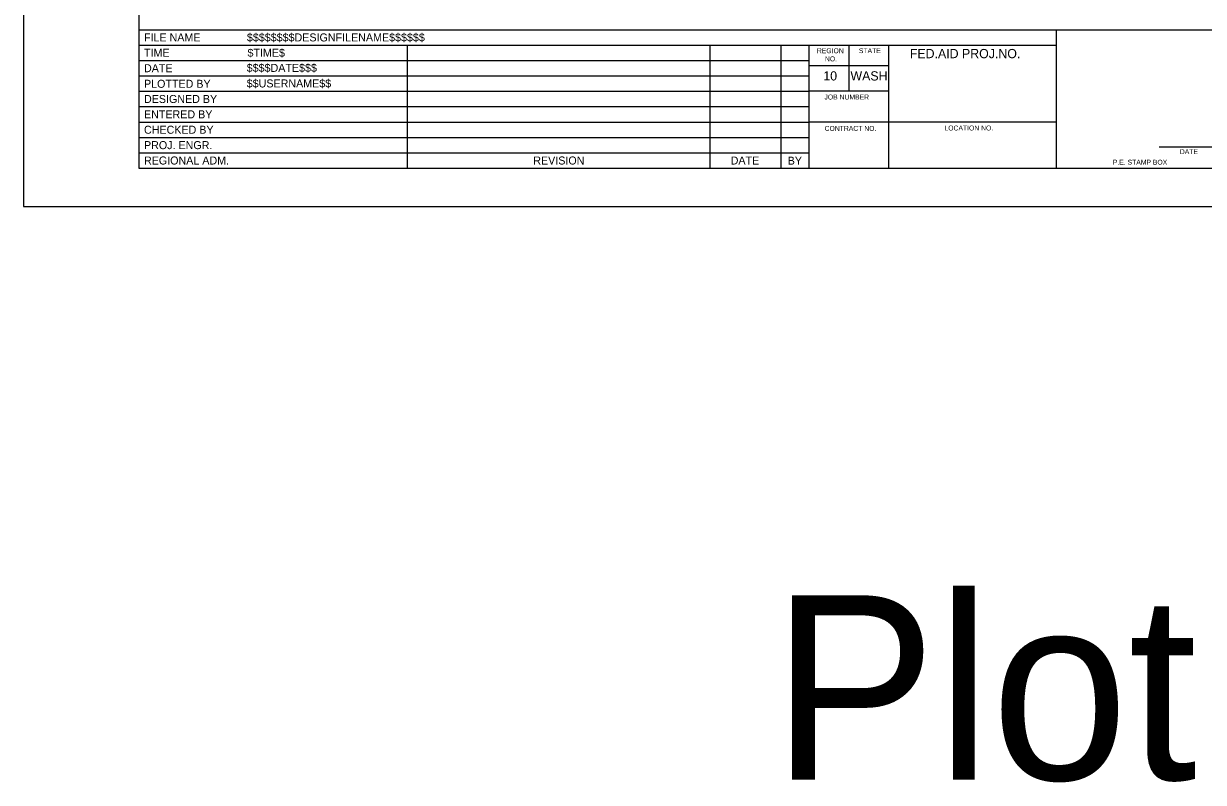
# Model space of a CAD drawing. Extents: x 99999.1 to 100035.7, y 99995 to 100010.7.
# Drawn here: x 99999.06 to 100008.65, y 99995.01 to 100001.18 of the extents above; entities that cross this region are included whole.
import ezdxf

# ---------------------------------------------------------------- set-up
doc = ezdxf.new("R2010")
doc.units = 0
for name, color, linetype in [('SH_GI_PlotLimits', 7, 'Continuous'), ('SH_GI_SheetBorder', 7, 'Continuous'), ('SH_GI_SheetLocationText', 7, 'Continuous'), ('SH_GI_SheetTextInCells', 7, 'Continuous'), ('SH_GI_TitleBlockText', 7, 'Continuous')]:
    doc.layers.add(name, color=color, linetype=linetype)

msp = doc.modelspace()

# ---------------------------------------------------------------- linework, layer by layer
at = {"layer": 'SH_GI_PlotLimits'}
msp.add_lwpolyline([(99999.0625, 99999.6875), (100016.0625, 99999.6875), (100016.0625, 100010.6875), (99999.0625, 100010.6875)], close=True, dxfattribs=at)
at = {"layer": 'SH_GI_SheetBorder'}
for p, q in [((100000, 100010.375), (100000, 100000)), ((100000, 100001.1259), (100015.75, 100001.1259)), ((100007.4566, 100000), (100007.4566, 100001.1259)), ((100000, 100001.0008), (100007.4566, 100001.0008)), ((100002.179, 100001.0008), (100002.179, 100000)), ((100004.641, 100001.0008), (100004.641, 100000)), ((100005.2164, 100001.0008), (100005.2164, 100000)), ((100005.4451, 100001.0008), (100005.4451, 100000)), ((100005.7719, 100000.6255), (100005.7719, 100001.0008)), ((100006.0956, 100000), (100006.0956, 100001.0008)), ((100000, 100000.8757), (100002.1821, 100000.8757)), ((100002.1821, 100000.8757), (100005.4466, 100000.8757)), ((100000, 100000.7506), (100002.1821, 100000.7506)), ((100002.1821, 100000.7506), (100005.4466, 100000.7506)), ((100006.0958, 100000.831), (100005.4466, 100000.831)), ((100000, 100000.6255), (100005.4466, 100000.6255)), ((100006.0958, 100000.6255), (100005.4466, 100000.6255)), ((100000, 100000.5004), (100005.4466, 100000.5004)), ((100000, 100000.3753), (100005.4466, 100000.3753)), ((100007.4566, 100000.3753), (100005.4466, 100000.3753)), ((100000, 100000.2502), (100005.4466, 100000.2502)), ((100008.2903, 100000.1733), (100008.802, 100000.1733)), ((100000, 100000.1251), (100005.4466, 100000.1251)), ((100000, 100000), (100015.75, 100000))]:
    msp.add_line(p, q, dxfattribs=at)

# ---------------------------------------------------------------- texts
at = {"layer": 'SH_GI_SheetLocationText'}
msp.add_text('Plot 1', height=1.5, dxfattribs=at).set_placement((100005.1422, 99995.0267))
at = {"layer": 'SH_GI_SheetTextInCells'}
for s, height, p in [('FILE NAME', 0.06505, (100000.041, 100001.0308)), ('TIME', 0.06505, (100000.041, 100000.9057)), ('REGION', 0.04003, (100005.5099, 100000.9352)), ('STATE', 0.04003, (100005.8511, 100000.9357)), ('FED.AID PROJ.NO.', 0.07506, (100006.2652, 100000.8945)), ('DATE', 0.06505, (100000.041, 100000.7806)), ('NO.', 0.04003, (100005.5752, 100000.869)), ('10', 0.07506, (100005.5621, 100000.7131)), ('WASH', 0.07506, (100005.7826, 100000.7131)), ('PLOTTED BY', 0.06505, (100000.041, 100000.6538)), ('DESIGNED BY', 0.065052, (100000.041, 100000.5304)), ('JOB NUMBER', 0.04003, (100005.5712, 100000.5587)), ('ENTERED BY', 0.06505, (100000.041, 100000.4053)), ('CHECKED BY', 0.06505, (100000.041, 100000.2802)), ('CONTRACT NO.', 0.040032, (100005.5725, 100000.3037)), ('LOCATION NO.', 0.040032, (100006.5465, 100000.3067)), ('PROJ. ENGR.', 0.065052, (100000.041, 100000.1551)), ('REGIONAL ADM.', 0.065052, (100000.041, 100000.03)), ('REVISION', 0.06505, (100003.2048, 100000.03)), ('DATE', 0.06505, (100004.8091, 100000.03)), ('BY', 0.06505, (100005.2725, 100000.0285)), ('P.E. STAMP BOX', 0.040032, (100007.915, 100000.0286)), ('DATE', 0.04003, (100008.4597, 100000.1141))]:
    msp.add_text(s, height=height, dxfattribs=at).set_placement(p)
at = {"layer": 'SH_GI_TitleBlockText'}
for s, height, p in [('$$$$$$$$DESIGNFILENAME$$$$$$', 0.065052, (100000.8775, 100001.0308)), ('$TIME$', 0.06505, (100000.882, 100000.9059)), ('$$$$DATE$$$', 0.065052, (100000.8759, 100000.7835)), ('$$USERNAME$$', 0.065052, (100000.8759, 100000.6567))]:
    msp.add_text(s, height=height, dxfattribs=at).set_placement(p)

doc.saveas('drawing.dxf')
